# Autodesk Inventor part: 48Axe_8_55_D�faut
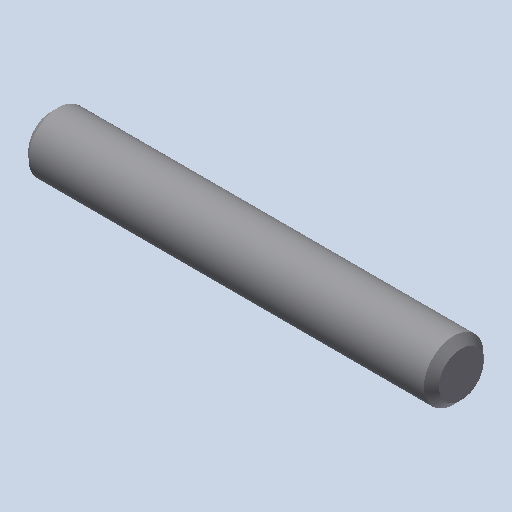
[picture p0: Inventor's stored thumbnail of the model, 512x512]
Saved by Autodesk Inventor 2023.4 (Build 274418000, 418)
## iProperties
Created: 2011-01
Part Number: 48Axe_8_55_D�faut
Document SubType Name: Modeling
Designer: eric
Density: 1 g/cm^3
Mass: 2.74156 g
Surface Area: 14.5078 cm^2
Volume: 2.74156 cm^3
Material: Générique
Appearance: Par défaut
Author: eric
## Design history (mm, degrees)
feature "Base1"
node "Corps solides"
node "Corps surfaciques"
node "Solide1"
